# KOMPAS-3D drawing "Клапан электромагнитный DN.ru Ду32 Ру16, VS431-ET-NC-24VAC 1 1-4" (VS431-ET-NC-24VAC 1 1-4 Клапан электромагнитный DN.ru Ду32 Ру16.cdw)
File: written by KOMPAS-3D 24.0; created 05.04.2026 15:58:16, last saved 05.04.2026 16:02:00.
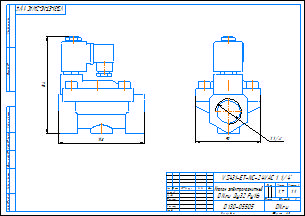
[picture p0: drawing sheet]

Document properties: c3d_UniqueCompID: ef56311e-7521-43dc-8291-0e6108b3d81d; Автор: artio; Класс точности: c; Знак неуказанной шероховатости: Шероховатость не задана; Рассекать на разрезах: Да; c3d_UniqueCompID: ef56311e-7521-43dc-8291-0e6108b3d81d; Автор: artio; Класс точности: c; Знак неуказанной шероховатости: Шероховатость не задана; Рассекать на разрезах: Да; c3d_UniqueCompID: ef56311e-7521-43dc-8291-0e6108b3d81d; Автор: artio; Класс точности: c; Знак неуказанной шероховатости: Шероховатость не задана; Рассекать на разрезах: Да; Автор: artio; Форматы листов документа: A3; Полное имя файла: VS431-ET-NC-24VAC 1 1-4 Клапан электромагнитный DN.ru Ду32 Ру16.m3d; Масса: 1.701; Наименование: Клапан электромагнитный DN.ru Ду32 Ру16; Количество листов документа: 1; Примечание: D130-05505

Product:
- Body: Тело 1  | qty 1
    Масса: 3.709873
- Part/product: Клапан электромагнитный DN.ru Ду32 Ру16  | designation VS431-ET-NC-24VAC 1 1-4
    Масса: 1.701
    Раздел спецификации: Прочие изделия
    Примечание: D130-05505
    additional columns: ef56311e-7521-43dc-8291-0e6108b3d81d; artio; c; Шероховатость не задана; Да

Views: Вид 1, Спереди
Referenced files in C:\Users\artio\OneDrive\Рабочий стол\Клапан электромагнитный DN.ru\VS431\VS431-ET-NC\: VS431-ET-NC-24VAC 3-4 Клапан электромагнитный DN.ru Ду20 Ру16.m3d, VS431-ET-NC-24VAC 1 1-4 Клапан электромагнитный DN.ru Ду32 Ру16.m3d, VS431-ET-NC-24VAC 3-4 Клапан электромагнитный DN.ru Ду20 Ру16.cdw
Referenced files in C:\Users\artio\OneDrive\Рабочий стол\Клапан электромагнитный DN.ru\VS431\VS431-ET-NC\VS431-ET-NC-24VAC\Ду32\: VS431-ET-NC-24VAC 1 1-4 Клапан электромагнитный DN.ru Ду32 Ру16.m3d
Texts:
  VS431-ET-NC-24VAC 1 1-4
  Клапан электромагнитный
  DN.ru Ду32 Ру16
  VS431-ET-NC-24VAC 1 1/4"
  VS431-ET-NC-24VAC 1 1/4"-
  Клапан электромагнитный DN.ru Ду32 Ру16
  VS431-ET-NC-24VAC 1 1-4 Клапан электромагнитный DN.ru Ду32 Ру16
Dimensions and other numbers on the sheet: 0; 3; 2; 4; 90; 1 1/4"; 1:1; 1; 1,7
